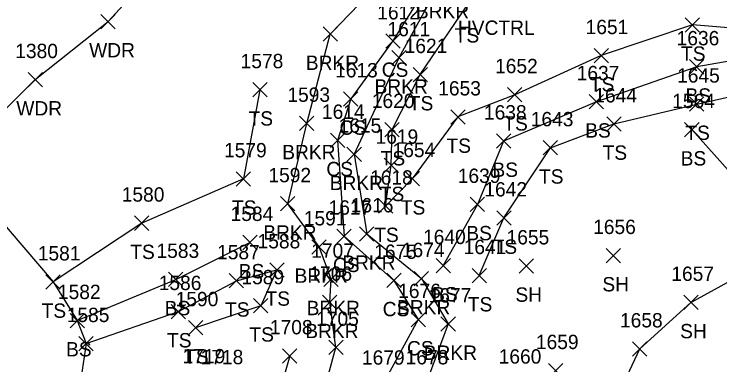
# Model space of a CAD drawing. Extents: x 1526508 to 1531550, y 369926 to 373082.
# Drawn here: x 1530976.9 to 1531075.3, y 370009.2 to 370058.1 of the extents above; entities that cross this region are included whole.
import ezdxf

# ---------------------------------------------------------------- set-up
doc = ezdxf.new("R2010")
doc.units = 0
for name, color, linetype in [('C_A', 7, 'Continuous'), ('L_A', 7, 'Continuous'), ('L_I', 7, 'Continuous'), ('L_TIC', 7, 'Continuous'), ('LAWA', 7, 'Continuous'), ('LAWE', 7, 'Continuous'), ('LELB', 7, 'Continuous'), ('LSOGP', 7, 'Continuous')]:
    doc.layers.add(name, color=color, linetype=linetype)

msp = doc.modelspace()

# ---------------------------------------------------------------- linework, layer by layer
at = {"layer": 'L_TIC'}
for points in [[(1530989.042, 370056.094), (1530991.042, 370058.094)], [(1530991.042, 370056.094), (1530989.042, 370058.094)], [(1531070.518, 370055.629), (1531072.518, 370057.629)], [(1531072.518, 370055.629), (1531070.518, 370057.629)], [(1531020.022, 370054.353), (1531022.022, 370056.353)], [(1531022.022, 370054.353), (1531020.022, 370056.353)], [(1531028.752, 370053.384), (1531030.752, 370055.384)], [(1531030.752, 370053.384), (1531028.752, 370055.384)], [(1531029.602, 370051.039), (1531031.602, 370053.039)], [(1531031.602, 370051.039), (1531029.602, 370053.039)], [(1531057.802, 370051.338), (1531059.802, 370053.338)], [(1531059.802, 370051.338), (1531057.802, 370053.338)], [(1531071.111, 370049.779), (1531073.111, 370051.779)], [(1531073.111, 370049.779), (1531071.111, 370051.779)], [(1530978.881, 370047.994), (1530980.881, 370049.994)], [(1530980.881, 370047.994), (1530978.881, 370049.994)], [(1531032.568, 370048.701), (1531034.568, 370050.701)], [(1531034.568, 370048.701), (1531032.568, 370050.701)], [(1531010.218, 370046.585), (1531012.218, 370048.585)], [(1531012.218, 370046.585), (1531010.218, 370048.585)], [(1531045.74, 370045.894), (1531047.74, 370047.894)], [(1531047.74, 370045.894), (1531045.74, 370047.894)], [(1531022.869, 370045.306), (1531024.869, 370047.306)], [(1531024.869, 370045.306), (1531022.869, 370047.306)], [(1531057.121, 370044.913), (1531059.121, 370046.913)], [(1531059.121, 370044.913), (1531057.121, 370046.913)], [(1531071.122, 370044.579), (1531073.122, 370046.579)], [(1531073.122, 370044.579), (1531071.122, 370046.579)], [(1531037.815, 370042.783), (1531039.815, 370044.783)], [(1531039.815, 370042.783), (1531037.815, 370044.783)], [(1531016.735, 370041.895), (1531018.735, 370043.895)], [(1531018.735, 370041.895), (1531016.735, 370043.895)], [(1531028.641, 370041.031), (1531030.641, 370043.031)], [(1531030.641, 370041.031), (1531028.641, 370043.031)], [(1531059.58, 370041.813), (1531061.58, 370043.813)], [(1531061.58, 370041.813), (1531059.58, 370043.813)], [(1531070.435, 370041.017), (1531072.435, 370043.017)], [(1531072.435, 370041.017), (1531070.435, 370043.017)], [(1531021.036, 370039.527), (1531023.036, 370041.527)], [(1531023.036, 370039.527), (1531021.036, 370041.527)], [(1531044.19, 370039.434), (1531046.19, 370041.434)], [(1531046.19, 370039.434), (1531044.19, 370041.434)], [(1531050.718, 370038.487), (1531052.718, 370040.487)], [(1531052.718, 370038.487), (1531050.718, 370040.487)], [(1531023.354, 370037.592), (1531025.354, 370039.592)], [(1531025.354, 370037.592), (1531023.354, 370039.592)], [(1531028.514, 370036.051), (1531030.514, 370038.051)], [(1531030.514, 370036.051), (1531028.514, 370038.051)], [(1531007.914, 370034.154), (1531009.914, 370036.154)], [(1531009.914, 370034.154), (1531007.914, 370036.154)], [(1531031.448, 370034.182), (1531033.448, 370036.182)], [(1531033.448, 370034.182), (1531031.448, 370036.182)], [(1531014.092, 370030.681), (1531016.092, 370032.681)], [(1531016.092, 370030.681), (1531014.092, 370032.681)], [(1531027.743, 370030.349), (1531029.743, 370032.349)], [(1531029.743, 370030.349), (1531027.743, 370032.349)], [(1531040.547, 370030.588), (1531042.547, 370032.588)], [(1531042.547, 370030.588), (1531040.547, 370032.588)], [(1531044.244, 370028.698), (1531046.244, 370030.698)], [(1531046.244, 370028.698), (1531044.244, 370030.698)], [(1530993.726, 370027.977), (1530995.726, 370029.977)], [(1530995.726, 370027.977), (1530993.726, 370029.977)], [(1531025.106, 370026.484), (1531027.106, 370028.484)], [(1531027.106, 370026.484), (1531025.106, 370028.484)], [(1531008.82, 370025.281), (1531010.82, 370027.281)], [(1531010.82, 370025.281), (1531008.82, 370027.281)], [(1531021.957, 370026.162), (1531023.957, 370028.162)], [(1531023.957, 370026.162), (1531021.957, 370028.162)], [(1531018.456, 370024.658), (1531020.456, 370026.658)], [(1531020.456, 370024.658), (1531018.456, 370026.658)], [(1531059.47, 370023.462), (1531061.47, 370025.462)], [(1531061.47, 370023.462), (1531059.47, 370025.462)], [(1531012.582, 370021.462), (1531014.582, 370023.462)], [(1531014.582, 370021.462), (1531012.582, 370023.462)], [(1531035.786, 370022.064), (1531037.786, 370024.064)], [(1531037.786, 370022.064), (1531035.786, 370024.064)], [(1531047.348, 370022.013), (1531049.348, 370024.013)], [(1531049.348, 370022.013), (1531047.348, 370024.013)], [(1531040.794, 370020.665), (1531042.794, 370022.665)], [(1531042.794, 370020.665), (1531040.794, 370022.665)], [(1530981.367, 370019.775), (1530983.367, 370021.775)], [(1530983.367, 370019.775), (1530981.367, 370021.775)], [(1530998.487, 370020.132), (1531000.487, 370022.132)], [(1531000.487, 370020.132), (1530998.487, 370022.132)], [(1531006.935, 370019.94), (1531008.935, 370021.94)], [(1531008.935, 370019.94), (1531006.935, 370021.94)], [(1531020.134, 370020.146), (1531022.134, 370022.146)], [(1531022.134, 370020.146), (1531020.134, 370022.146)], [(1531028.889, 370019.999), (1531030.889, 370021.999)], [(1531030.889, 370019.999), (1531028.889, 370021.999)], [(1531032.741, 370020.245), (1531034.741, 370022.245)], [(1531034.741, 370020.245), (1531032.741, 370022.245)], [(1531010.337, 370016.458), (1531012.337, 370018.458)], [(1531012.337, 370016.458), (1531010.337, 370018.458)], [(1531019.947, 370016.944), (1531021.947, 370018.944)], [(1531021.947, 370016.944), (1531019.947, 370018.944)], [(1531070.317, 370016.923), (1531072.317, 370018.923)], [(1531072.317, 370016.923), (1531070.317, 370018.923)], [(1530998.851, 370015.646), (1531000.851, 370017.646)], [(1531000.851, 370015.646), (1530998.851, 370017.646)], [(1530984.746, 370014.395), (1530986.746, 370016.395)], [(1530986.746, 370014.395), (1530984.746, 370016.395)], [(1531032.283, 370014.536), (1531034.283, 370016.536)], [(1531034.283, 370014.536), (1531032.283, 370016.536)], [(1531036.461, 370013.917), (1531038.461, 370015.917)], [(1531038.461, 370013.917), (1531036.461, 370015.917)], [(1531001.245, 370013.392), (1531003.245, 370015.392)], [(1531003.245, 370013.392), (1531001.245, 370015.392)], [(1530985.97, 370011.18), (1530987.97, 370013.18)], [(1530987.97, 370011.18), (1530985.97, 370013.18)], [(1531020.821, 370010.641), (1531022.821, 370012.641)], [(1531022.821, 370010.641), (1531020.821, 370012.641)], [(1531014.379, 370009.47), (1531016.379, 370011.47)], [(1531016.379, 370009.47), (1531014.379, 370011.47)], [(1531063.161, 370010.436), (1531065.161, 370012.436)], [(1531065.161, 370010.436), (1531063.161, 370012.436)], [(1531051.441, 370007.417), (1531053.441, 370009.417)], [(1531053.441, 370007.417), (1531051.441, 370009.417)]]:
    msp.add_lwpolyline(points, dxfattribs=at)
at = {"layer": 'LAWA'}
msp.add_lwpolyline([(1530968.161, 370037.392), (1530979.881, 370048.994), (1530990.042, 370057.094), (1531002.64, 370070.867), (1531012.129, 370088.176), (1531024.743, 370101.609), (1531031.255, 370108.889), (1531038.675, 370107.681), (1531051.109, 370105.813), (1531063.824, 370101.61), (1531080.52, 370097.978), (1531114.388, 370088.681)], dxfattribs=at)
at = {"layer": 'LAWE'}
for points in [[(1531019.456, 370025.658), (1531015.092, 370031.681), (1531017.735, 370042.895), (1531021.022, 370055.353), (1531031.936, 370066.689), (1531036.959, 370075.792), (1531040.124, 370085.283), (1531045.475, 370094.519)], [(1531060.475, 370091.712), (1531052.156, 370080.261), (1531044.198, 370067.732), (1531036.367, 370062.528), (1531030.602, 370052.039), (1531024.354, 370038.592), (1531026.106, 370027.484), (1531033.741, 370021.245), (1531037.461, 370014.917), (1531034.276, 370006.285), (1531036.574, 370000.952), (1531037.909, 369989.716), (1531028.612, 369973.066), (1531021.32, 369966.868), (1531020.147, 369956.358), (1531019.718, 369949.927), (1531016.167, 369945.616)], [(1531021.134, 370021.146), (1531019.456, 370025.658)], [(1531002.404, 369959.398), (1531007.446, 369969.402), (1531011.329, 369974.195), (1531017.264, 369985.498), (1531022.995, 369992.828), (1531019.739, 370004.121), (1531021.821, 370011.641), (1531020.947, 370017.944), (1531021.134, 370021.146)]]:
    msp.add_lwpolyline(points, dxfattribs=at)
at = {"layer": 'LELB'}
for points in [[(1531052.195, 370093.898), (1531049.718, 370088.151), (1531047.993, 370081.349), (1531041.848, 370072.074), (1531040.413, 370069.701), (1531036.278, 370064.915), (1531029.752, 370054.384), (1531023.869, 370046.306), (1531022.036, 370040.527), (1531022.957, 370027.162), (1531029.889, 370020.999), (1531033.283, 370015.536), (1531028.189, 370006.244), (1531029.192, 369995.782), (1531030.035, 369991.3), (1531027.529, 369979.919), (1531018.741, 369970.401), (1531013.395, 369964.149), (1531009.139, 369955.011)], [(1531028.743, 370031.349), (1531029.514, 370037.051), (1531029.641, 370042.031), (1531033.568, 370049.701), (1531039.965, 370059.168), (1531045.749, 370066.67), (1531051.339, 370074.535)], [(1531090.019, 370057.631), (1531083.289, 370055.66), (1531071.518, 370056.629), (1531058.802, 370052.338), (1531046.74, 370046.894), (1531038.815, 370043.783), (1531032.448, 370035.182)], [(1531094.983, 370055.347), (1531084.081, 370052.851), (1531072.111, 370050.779), (1531058.121, 370045.913), (1531045.19, 370040.434), (1531041.547, 370031.588), (1531036.786, 370023.064)], [(1531041.794, 370021.665), (1531045.244, 370029.698), (1531051.718, 370039.487), (1531060.58, 370042.813), (1531072.122, 370045.579), (1531081.58, 370047.706), (1531098.567, 370051.414)], [(1531011.218, 370047.585), (1531008.914, 370035.154), (1530994.726, 370028.977), (1530982.367, 370020.775)], [(1531085.82, 370025.922), (1531071.435, 370042.017)], [(1531032.448, 370035.182), (1531028.743, 370031.349)], [(1530985.746, 370015.395), (1530999.487, 370021.132), (1531009.82, 370026.281)], [(1530986.97, 370012.18), (1530999.851, 370016.646), (1531007.935, 370020.94), (1531013.582, 370022.462), (1531011.337, 370017.458), (1531002.245, 370014.392)], [(1531015.379, 370010.47), (1531013.178, 370002.812), (1531012.386, 369997.677), (1531009.872, 369991.787), (1530999.516, 369989.286), (1530995.267, 369985.757), (1530986.205, 369973.777)]]:
    msp.add_lwpolyline(points, dxfattribs=at)
at = {"layer": 'LSOGP'}
for points in [[(1530968.161, 370037.392), (1530982.367, 370020.775), (1530985.746, 370015.395), (1530986.97, 370012.18), (1530984.907, 369998.254)], [(1531057.51, 369997.199), (1531064.161, 370011.436), (1531071.317, 370017.923), (1531085.82, 370025.922), (1531106.609, 370027.813), (1531116.761, 370026.858), (1531124.22, 370028.071), (1531130.42, 370028.943), (1531141.717, 370028.659), (1531148.632, 370028.784)]]:
    msp.add_lwpolyline(points, dxfattribs=at)

# ---------------------------------------------------------------- texts
at = {"layer": 'C_A'}
msp.add_text('HVCTRL', height=2, dxfattribs=at).set_placement((1531038.82, 370055.237))
at = {"layer": 'L_A'}
for s, p in [('BRKR', (1531032.957, 370057.528)), ('TS', (1531038.374, 370054.168)), ('WDR', (1530987.404, 370052.094)), ('TS', (1531069.927, 370051.629)), ('BRKR', (1531017.613, 370050.353)), ('CS', (1531028.193, 370049.384)), ('BRKR', (1531027.193, 370047.039)), ('TS', (1531057.211, 370047.338)), ('BS', (1531070.552, 370045.779)), ('WDR', (1530977.244, 370043.994)), ('TS', (1531031.977, 370044.701)), ('TS', (1531009.627, 370042.585)), ('CS', (1531022.31, 370041.306)), ('TS', (1531045.149, 370041.894)), ('BS', (1531056.562, 370040.913)), ('TS', (1531070.531, 370040.579)), ('TS', (1531037.225, 370038.783)), ('BRKR', (1531014.326, 370037.895)), ('TS', (1531028.051, 370037.031)), ('TS', (1531058.99, 370037.813)), ('BS', (1531069.876, 370037.017)), ('CS', (1531020.477, 370035.527)), ('BS', (1531043.631, 370035.434)), ('TS', (1531050.127, 370034.487)), ('BRKR', (1531020.945, 370033.592)), ('TS', (1531027.923, 370032.051)), ('TS', (1531007.323, 370030.154)), ('TS', (1531030.858, 370030.182)), ('BRKR', (1531011.682, 370026.681)), ('TS', (1531027.153, 370026.349)), ('BS', (1531039.988, 370026.588)), ('TS', (1531043.653, 370024.698)), ('TS', (1530993.136, 370023.977)), ('BRKR', (1531022.696, 370022.484)), ('BS', (1531008.261, 370021.281)), ('CS', (1531021.398, 370022.162)), ('BRKR', (1531016.046, 370020.658)), ('SH', (1531058.958, 370019.462)), ('TS', (1531011.992, 370017.462)), ('BS', (1531035.227, 370018.064)), ('SH', (1531046.836, 370018.013)), ('TS', (1531040.203, 370016.665)), ('TS', (1530980.776, 370015.775)), ('BS', (1530997.928, 370016.132)), ('TS', (1531006.345, 370015.94)), ('BRKR', (1531017.725, 370016.146)), ('CS', (1531028.33, 370015.999)), ('BRKR', (1531030.332, 370016.245)), ('TS', (1531009.746, 370012.458)), ('BRKR', (1531017.537, 370012.944)), ('SH', (1531069.805, 370012.923)), ('TS', (1530998.261, 370011.646)), ('CS', (1531031.724, 370010.536)), ('BS', (1530984.187, 370010.395)), ('BRKR', (1531034.051, 370009.917)), ('TS', (1531000.655, 370009.392))]:
    msp.add_text(s, height=2, dxfattribs=at).set_placement(p)
at = {"layer": 'L_I'}
for s, p in [('1612', (1531027.579, 370057.384)), ('1611', (1531028.996, 370055.039)), ('1651', (1531056.628, 370055.338)), ('1636', (1531069.316, 370053.779)), ('1380', (1530977.102, 370051.994)), ('1621', (1531031.394, 370052.701)), ('1578', (1531008.525, 370050.585)), ('1652', (1531043.999, 370049.894)), ('1613', (1531021.696, 370049.306)), ('1637', (1531055.381, 370048.913)), ('1645', (1531069.382, 370048.579)), ('1593', (1531015.042, 370045.895)), ('1653', (1531036.075, 370046.783)), ('1620', (1531026.814, 370045.031)), ('1644', (1531057.84, 370045.813)), ('1564', (1531068.695, 370045.017)), ('1614', (1531019.863, 370043.527)), ('1638', (1531042.45, 370043.434)), ('1643', (1531048.978, 370042.487)), ('1615', (1531022.181, 370041.592)), ('1619', (1531027.332, 370040.051)), ('1579', (1531006.213, 370038.154)), ('1654', (1531029.708, 370038.182)), ('1592', (1531012.399, 370034.681)), ('1618', (1531026.57, 370034.349)), ('1639', (1531038.799, 370034.588)), ('1642', (1531042.504, 370032.698)), ('1580', (1530991.947, 370031.977)), ('1617', (1531020.784, 370030.162)), ('1616', (1531023.877, 370030.484)), ('1584', (1531007.127, 370029.281)), ('1591', (1531017.33, 370028.658)), ('1656', (1531057.675, 370027.462)), ('1588', (1531010.889, 370025.462)), ('1640', (1531033.959, 370026.064)), ('1655', (1531045.607, 370026.013)), ('1674', (1531031.001, 370024.245)), ('1641', (1531039.621, 370024.665)), ('1581', (1530980.241, 370023.775)), ('1583', (1530996.794, 370024.132)), ('1587', (1531005.242, 370023.94)), ('1707', (1531018.363, 370024.146)), ('1675', (1531027.149, 370023.999)), ('1589', (1531008.636, 370020.458)), ('1706', (1531018.12, 370020.944)), ('1657', (1531068.577, 370020.923)), ('1586', (1530997.103, 370019.646)), ('1582', (1530983.053, 370018.395)), ('1676', (1531030.488, 370018.536)), ('1590', (1530999.466, 370017.392)), ('1677', (1531034.721, 370017.917)), ('1585', (1530984.277, 370015.18)), ('1705', (1531019.049, 370014.641)), ('1658', (1531061.42, 370014.436)), ('1708', (1531012.607, 370013.47)), ('1659', (1531049.693, 370011.417)), ('1719', (1531000.435, 370009.428)), ('1718', (1531002.946, 370009.31)), ('1679', (1531025.441, 370009.244)), ('1678', (1531031.536, 370009.285)), ('1660', (1531044.506, 370009.389))]:
    msp.add_text(s, height=2, dxfattribs=at).set_placement(p)

doc.saveas('drawing.dxf')
